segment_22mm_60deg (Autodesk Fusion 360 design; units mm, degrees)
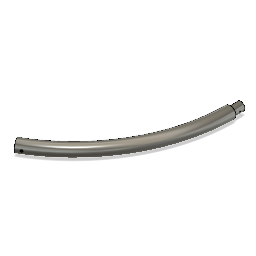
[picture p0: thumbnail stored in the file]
sketch "profile25mm" plane through (0, 0, 0) normal (0, 0, 1) x axis (1, 0, 0)
  line L1 (307.6864, 0) -> (0, 0)
  line L2 (284.5852, 6.2462) -> (284.5852, -6.2452)
  line L3 (286.5852, -8.1498) -> (286.5852, 8.1498)
  line L4 (286.6852, -8.0748) -> (286.6852, 8.0748)
  line L5 (288.5852, -6.4868) -> (288.5852, 6.4868)
  line L6 (281.1852, 6.0452) -> (281.1852, 6.2452)
  line L7 (280.7852, 5.8452) -> (280.9852, 5.8452)
  line L8 (280.3368, 6.812) -> (280.7852, 7.3155)
  line L9 (281.1852, -6.0452) -> (281.1852, -6.2452)
  line L10 (280.7852, -5.8452) -> (280.9852, -5.8452)
  line L11 (280.3368, -6.812) -> (280.7852, -7.3155)
  line L12 (284.1852, 5.6456) -> (284.1852, 6.2456)
  line L13 (282.5852, 5.4456) -> (283.9852, 5.4456)
  line L14 (282.3852, 6.2456) -> (282.3852, 5.6456)
  line L15 (284.1852, -5.6452) -> (284.1852, -6.2452)
  line L16 (282.5852, -5.4452) -> (283.9852, -5.4452)
  line L17 (282.3852, -6.2452) -> (282.3852, -5.6452)
  line L18 (282.3852, 6.2456) -> (281.1852, 6.2452)
  line L19 (284.5852, 6.2462) -> (284.1852, 6.2456)
  line L20 (282.3852, -6.2452) -> (281.1852, -6.2452)
  line L21 (284.5852, -6.2452) -> (284.1852, -6.2452)
  arc A1 centre (289, 0) radius 8.5 clockwise from (286.5852, 8.1498) to (286.5852, -8.1498)
  arc A2 centre (289, 0) radius 11 clockwise from (280.7852, 7.3155) to (280.7852, -7.3155)
  arc A3 centre (289, 0) radius 8.4 clockwise from (286.6852, 8.0748) to (286.6852, -8.0748)
  arc A4 centre (289, 0) radius 6.5 clockwise from (288.5852, 6.4868) to (288.5852, -6.4868)
  arc A5 centre (280.7705, 6.4258) radius 0.5808 clockwise from (280.7852, 5.8452) to (280.3368, 6.812)
  arc A6 centre (280.7705, -6.4258) radius 0.5808 clockwise from (280.3368, -6.812) to (280.7852, -5.8452)
  arc A7 centre (282.5852, 5.6456) radius 0.2 clockwise from (282.5852, 5.4456) to (282.3852, 5.6456)
  arc A8 centre (283.9852, 5.6456) radius 0.2 clockwise from (284.1852, 5.6456) to (283.9852, 5.4456)
  arc A9 centre (282.5852, -5.6452) radius 0.2 clockwise from (282.3852, -5.6452) to (282.5852, -5.4452)
  arc A10 centre (283.9852, -5.6452) radius 0.2 clockwise from (283.9852, -5.4452) to (284.1852, -5.6452)
  arc A11 centre (280.9852, -6.0452) radius 0.2 clockwise from (280.9852, -5.8452) to (281.1852, -6.0452)
  arc A12 centre (280.9852, 6.0452) radius 0.2 clockwise from (281.1852, 6.0452) to (280.9852, 5.8452)
  point P1 (0, 0)
  point P3 (0, 0)
  point P2 (289, 0)
  point P17 (280.7852, 7.3155)
  point P26 (280.7852, -7.3155)
  point P19 (280.7852, 5.8452)
  point P23 (280.7852, -5.8452)
  point P20 (280.3368, 6.812)
  point P25 (280.3368, -6.812)
  point P29 (282.3852, 5.4456)
  point P33 (282.3852, -5.4452)
  point P32 (284.1852, -5.4452)
  point P7 (289, 0)
  point P27 (282.3852, 6.2456)
  point P28 (284.1852, 6.2456)
  point P30 (282.3852, -6.2452)
  coincident P1 P3
  horizontal L1
  coincident P2 L1
  concentric A1 A2
  perpendicular L1 L3
  horizontal L20
  vertical L6
  horizontal L7
  tangent A2 L8
  tangent L8 A5
  vertical L9
  horizontal L10
  symmetric L1 P17 P26
  symmetric L1 P19 P23
  symmetric L1 P20 P25
  symmetric L1 A5 A6
  vertical L12
  horizontal L13
  vertical L14
  vertical L15
  horizontal L16
  vertical L17
  coincident P29 L13
  coincident P29 L14
  tangent L13 A7
  tangent L14 A7
  tangent L12 A8
  tangent L13 A8
  equal A7 A8
  coincident P33 L16
  coincident P33 L17
  tangent L16 A9
  tangent L17 A9
  equal A7 A9
  coincident P32 L15
  coincident P32 L16
  tangent L15 A10
  tangent L16 A10
  equal A7 A10
  tangent L9 A11
  tangent L10 A11
  equal A7 A11
  tangent L6 A12
  tangent L7 A12
  equal A7 A12
  collinear L20 L21
  dimension "d1" diameter A2 = 22
  dimension "d5" diameter A1 = 17
  dimension "d10" distance L2 L3 = 2
  dimension "d11" = -0.1
  dimension "d12" = -2
  dimension "d13" distance P1 P7 = 289
  dimension "d58" distance P27 P28 = 1.8
  dimension "d59" distance P27 P29 = 0.8
  dimension "d60" distance L2 L12 = 0.4
  dimension "d61" distance P32 P33 = 1.8
  dimension "d62" distance P30 P33 = 0.8
  dimension "d63" distance L2 L15 = 0.4
  dimension "d64" radius A7 = 0.2
revolve "Revolve1" sketch "profile25mm" AlongAngle 60 bodies "profile"
revolve "Revolve2" sketch "profile25mm" AlongAngle 4
revolve "Revolve3" sketch "profile25mm" AlongAngle -4
chamfer "Chamfer1" distance 1
chamfer "Chamfer2" distance 1.9
work_plane "WorkPlane1"
sketch "middle plane" plane through (272.3575, 0.0002, 35.882) normal (0, -1, 0) x axis (1, 0, 0)
  line L1 (-131.9649, 207.2851) -> (-122.3575, 223.9256)
  line L2 (14.6269, -55.9499) -> (23.3204, -56.5578)
  line L3 (13.6973, -54.8824) -> (14.6269, -55.9499)
  line L4 (25.0425, -35.882) -> (27.6425, -35.882)
  line L5 (8.4277, -35.882) -> (14.3277, -35.882)
  line L6 (24.3861, -55.6299) -> (23.3204, -56.5578)
  line L7 (-115.0265, 216.6233) -> (-113.7806, 218.7813)
  line L8 (17.5, -45.882) -> (24.8743, -45.882)
  line L9 (-132.1891, 206.8968) -> (-131.9649, 207.2851)
  line L10 (-132.2627, 206.7695) -> (-132.1891, 206.8968)
  line L11 (7.8322, -35.882) -> (7.9792, -35.882)
  line L12 (7.9792, -35.882) -> (8.4277, -35.882)
  arc A1 centre (-272.3575, -35.882) radius 286.6852 clockwise from (14.3277, -35.882) to (13.6973, -54.8824)
  arc A2 centre (-272.3575, -35.882) radius 297.4 clockwise from (25.0425, -35.882) to (24.3861, -55.6299)
  arc A3 centre (-272.3575, -35.882) radius 300 clockwise from (-122.3575, 223.9256) to (27.6425, -35.882)
  arc A4 centre (-272.3575, -35.882) radius 280.1897 clockwise from (-132.2627, 206.7695) to (7.8322, -35.882)
  point P14 (-113.7806, 218.7813)
  point P16 (24.8743, -45.882)
  coincident A3 P14
  parallel L1 L7
  coincident A2 P16
  parallel L4 L8
  dimension "d25" distance L1 L7 = 10
  dimension "d33" distance L4 L8 = 10
work_plane "WorkPlane2"
sketch "hole1" plane through (158.5769, 0.0002, 254.6632) normal (0.5286, 0, 0.8489) x axis (0, 1, 0)
  circle C1 centre (0, 0) radius 2.05
  circle C2 centre (0, 0) radius 1.05
  point P1 (0, 0)
  point P2 (0, 0)
  coincident P1 P2
  concentric C1 C2
  dimension "d26" diameter C1 = 4.1
  dimension "d27" diameter C2 = 2.1
extrude "Extrude2" cut sketch "hole1" along a picked direction blind -1
extrude "Extrude3" cut sketch "hole1" profile of C2 along a picked direction blind -3
work_plane "WorkPlane3"
sketch "hole2" plane through (297.2318, 0.0002, -10) normal (0.9994, 0, -0.0336) x axis (0, 1, 0)
  line L1 (0, 2.3094) -> (2, 1.1547)
  line L2 (-2, 1.1547) -> (0, 2.3094)
  line L3 (-2, -1.1547) -> (-2, 1.1547)
  line L4 (0, -2.3094) -> (-2, -1.1547)
  line L5 (2, -1.1547) -> (0, -2.3094)
  line L6 (2, 1.1547) -> (2, -1.1547)
  circle C1 centre (0, 0) radius 1.05
  circle C2 centre (0, 0) radius 4
  point P1 (0, 0)
  point P2 (0, 0)
  point P3 (0, 0)
  point P10 (0, 0)
  coincident P1 P2
  coincident P1 P3
  coincident P3 P10
  dimension "d34" diameter C1 = 2.1
  dimension "d37" diameter C2 = 8
extrude "Extrude4" cut sketch "hole2" profile of C1 against normal blind 3
extrude "Extrude5" add sketch "hole2" profile of C2 L1 L2 L3 L4 L5 L6 blind -1.6 from offset -2
chamfer "Chamfer3" distance 0.5
named bodies: "profile"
